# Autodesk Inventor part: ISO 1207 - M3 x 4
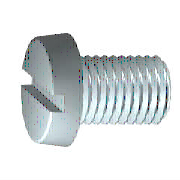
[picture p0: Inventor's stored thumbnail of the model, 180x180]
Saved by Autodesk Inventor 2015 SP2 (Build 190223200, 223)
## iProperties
IsCustomPart: 0
Created: 2012-02
Part Number: ISO 1207 - M3 x 4
Material: Edelstahl, 440C
Description: Zylinderkopfschrauben mit Schlitz - Produktklasse A
Document SubType Name: Modeling
Standard: ISO 1207
Designer: rYan
Standard Revision: Third edition 1992-05-15
Standards Organization: ISO
Language: de-DE
Size Designation: M3 x 4
Categories: <MemberInstance><Categories><Category DisplayName="Verbindungselemente" InternalName="e4da775c-781d-43d5-af7c-5136215cf5a6" Mnemonic="FSTN"><Category DisplayNam
Density: 7.75 g/cm^3
Appearance: Halbpoliert
Author: rYan
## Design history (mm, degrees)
body "Solid1"
revolve "Körper" stored, may be unused: angle "d8" = 90 deg
sketch "Skizze2"
  geometry: L1 (0, 0)-(0, 2.575) reference; L2 (-2.75, 0.4)-(2.75, 0.4); L3 (2.75, 0.4)-(2.75, -0.4); L4 (2.75, -0.4)-(-2.75, -0.4); L5 (-2.75, -0.4)-(-2.75, 0.4); L6 (-2.75, 0)-(2.75, 0); L7 (0, 0.4)-(0, -0.4); C1 r 2.75 at (0, 0) reference; 1 further point
  constraints: 12 end point, 5 midpoint, 2 parallel, 1 collinear, 1 horizontal, 1 perpendicular
  dimensions: "d11" = 0.8 distance of L4.end L2.start (= SBR); "d12" = 5.5 distance of L2.start L2.end (= KOD)
fillet "Rundung1" dims "d14" = 0.1 (= RR)
extrude "Loch" cut sketch "Skizze2" distance "d19" = 0.85 (= STI); taper "d20" = 0 deg
feature "Gewinde" dims "d15" = 3 (= GEL), "d16" = 0
chamfer "Fase1" distance "d17" = 0.30673 (= -0.5 x SPD + 0.5 x GD); stored, may be unused: second distance "d18" = 0.30683 (computed from GUL), angle "d36" = 45 deg
workplane "Work Plane1"
sketch "Skizze1"
  geometry: L1 (-2, 0)-(4, 0); L2 (4, 0)-(4, 1.5); L3 (4, 1.5)-(1, 1.5); L4 (1, 1.5)-(0.693, 1.347); L5 (0.693, 1.347)-(0, 1.347); L6 (0, 1.347)-(0, 2.75); L7 (-3.2, 0)-(5.2, 0) reference; L8 (0, -0.55)-(0, 3.3) reference; L9 (-2, 0)-(-2, 2.575); L10 (0, 2.75)-(-2, 2.575); L11 (1, 1.5)-(0, 1.5)
  constraints: 18 end point, 4 parallel, 2 collinear, 2 perpendicular, 1 horizontal, 1 point on line
  dimensions: "d0" = 4 distance between parallel lines of L2 L6 (= NLG); "d1" = 3 distance from line of L3.end L2 (= GEL); "d2" = 0.30683 horizontal distance of L4.end L3.end (computed from GAL); "d3" = 2 distance from line of L1.start L6 (= KOH); "d4" = 3 diameter of L3 L1 (= GD); "d5" = 2.6935 diameter of L5 L1 (= BDM); "d9" = 5.5 diameter of L6.end L1 (= KOD); "d10" = 5 deg angle of L10 L1 (= KEWI)
other parameters: "GD" = 3 (= NND) [user parameter; used in 2 equation terms], "NLG" = 4 [user parameter; used in 1 equation term], "GEL" = 3 [user parameter; used in 2 equation terms], "KOD" = 5.5 [user parameter; used in 2 equation terms], "KOH" = 2 [user parameter; used in 1 equation term], "GAL" = 0.30673 (= 0.61345 x PTC) [user parameter; used in 1 equation term], "SPD" = 2.38655 (= NND - 1.2269 x PTC) [user parameter; used in 1 equation term], "BDM" = 2.6935 [user parameter; used in 1 equation term], "GUL" = 0.30673 (= 0.61345 x PTC) [user parameter; used in 1 equation term], "RR" = 0.1 [user parameter; used in 1 equation term], "d7" = 0, "SBR" = 0.8 [user parameter; used in 1 equation term], "STI" = 0.85 [user parameter; used in 1 equation term], "KEWI" = 5 deg [user parameter; used in 1 equation term], "d37" = 0, "d39" = 0, "PTC" = 0.5 [user parameter; used in 5 equation terms], "THREADDIA" = 3 [user parameter; used in 1 equation term], "TOA" = 30 deg [user parameter], "NND" = 3 [user parameter; used in 2 equation terms], "GD1" = 2.38655 (= THREADDIA - 1.2269 x PTC) [user parameter]
